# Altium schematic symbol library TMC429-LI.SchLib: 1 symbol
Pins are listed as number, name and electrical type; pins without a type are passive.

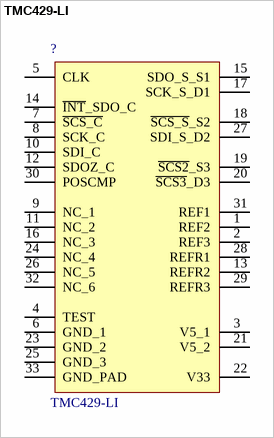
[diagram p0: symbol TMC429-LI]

## TMC429-LI
designator ?
Intelligent Triple Stepper Motor Controller with SPI, Step/Dir, QFN32(5x5); Manufacturer: TRINAMIC; Geometry.Height: 0,9mm; Ordercode - Distri#1: 1460-1071-1-ND; Ordercode - Distri#2: 1858310
footprint TMC_QFN32_0.5_5.0X5.0
pins: 1 REF2, 2 REF3, 3 V5_1 (power), 4 TEST, 5 CLK, 6 GND_1, 7 ~{SCS_C}, 8 SCK_C, 9 NC_1, 10 SDI_C, 11 NC_2, 12 SDOZ_C, 13 REFR2, 14 ~{INT}_SDO_C, 15 SDO_S_S1, 16 NC_3, 17 SCK_S_D1, 18 ~{SCS_S}_S2, 19 ~{SCS2}_S3, 20 ~{SCS3}_D3, 21 V5_2 (power), 22 V33 (power), 23 GND_2, 24 NC_4, 25 GND_3, 26 NC_5, 27 SDI_S_D2, 28 REFR1, 29 REFR3, 30 POSCMP, 31 REF1, 32 NC_6, 33 GND_PAD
